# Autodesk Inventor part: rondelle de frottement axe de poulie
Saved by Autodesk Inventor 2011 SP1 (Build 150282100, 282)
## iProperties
Created: 2010-12
Part Number: rondelle de frottement axe de poulie
Document SubType Name: Modeling
Designer: eric
Density: 1 g/cm^3
Mass: 0.0596746 g
Surface Area: 2.79853 cm^2
Volume: 0.0596746 cm^3
Author: eric
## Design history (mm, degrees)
feature "Base1"
node "Solide1"
node "Corps solides"
node "Corps surfaciques"
